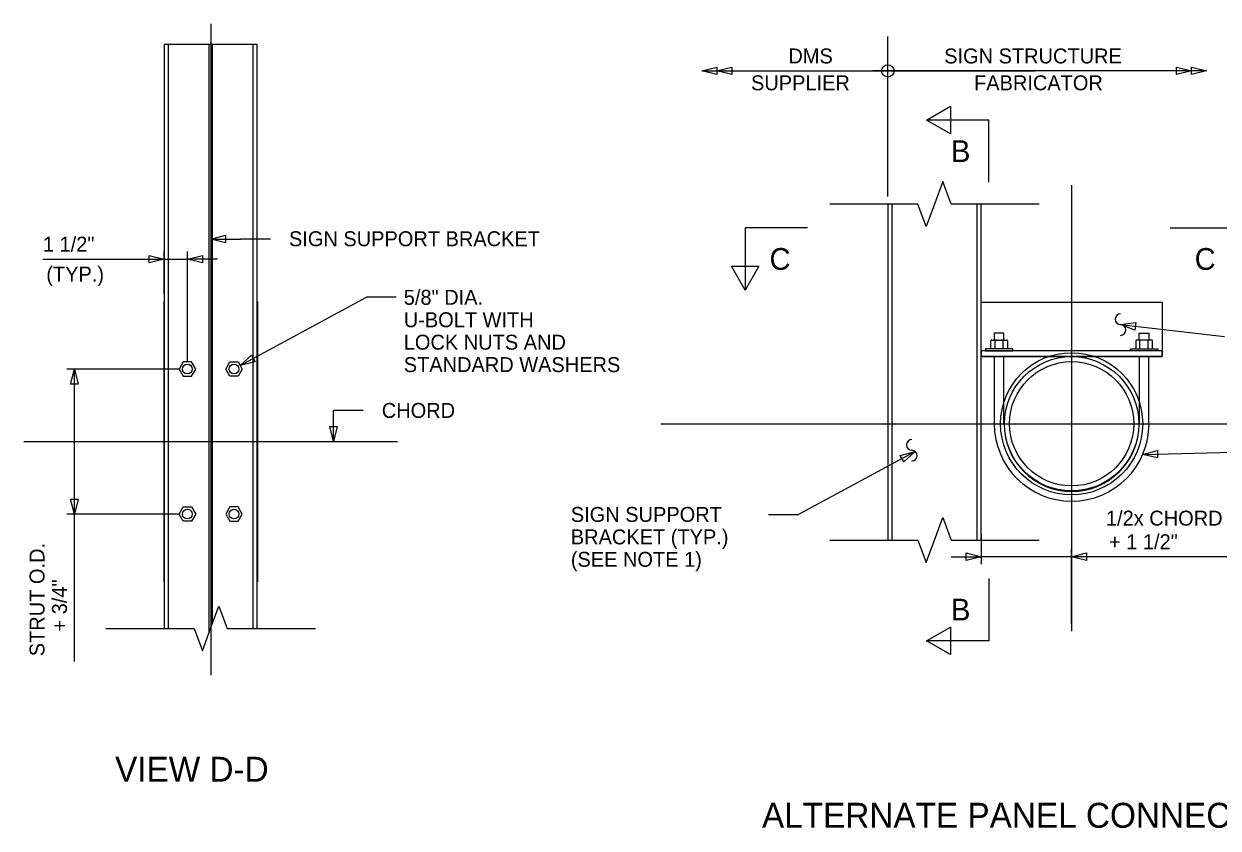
# Model space of a CAD drawing. Extents: x 3831399 to 3833095, y 499014 to 500202.
# Drawn here: x 3832557.6 to 3832797.3, y 499205.3 to 499366.6 of the extents above; entities that cross this region are included whole.
import ezdxf

# ---------------------------------------------------------------- set-up
doc = ezdxf.new("R2010")
doc.units = 0
for name, color, linetype in [('CNTR', 7, 'Continuous'), ('Default', 7, 'Continuous'), ('DIM TXT', 7, 'Continuous'), ('sign', 7, 'Continuous'), ('structure', 7, 'Continuous')]:
    doc.layers.add(name, color=color, linetype=linetype)

msp = doc.modelspace()

# ---------------------------------------------------------------- linework, layer by layer
at = {"layer": 'CNTR'}
for p, q in [((3832595.05, 499366.63), (3832595.05, 499235.97)), ((3832767.85, 499334.27), (3832767.85, 499244.83)), ((3832685.4, 499286.41), (3832811.96, 499286.41)), ((3832557.55, 499282.84), (3832632.55, 499282.84))]:
    msp.add_line(p, q, dxfattribs=at)
at = {"layer": 'Default'}
for p, q in [((3832738.75, 499347.35), (3832743.51, 499350.1)), ((3832743.51, 499350.1), (3832743.51, 499344.6)), ((3832743.51, 499344.6), (3832738.75, 499347.35)), ((3832702.32, 499313.23), (3832699.57, 499318)), ((3832699.57, 499318), (3832705.07, 499318)), ((3832705.07, 499318), (3832702.32, 499313.23)), ((3832738.75, 499242.89), (3832743.51, 499245.64)), ((3832743.51, 499245.64), (3832743.51, 499240.14)), ((3832743.51, 499240.14), (3832738.75, 499242.89))]:
    msp.add_line(p, q, dxfattribs=at)
at = {"layer": 'DIM TXT'}
for p, q in [((3832730.97, 499331.98), (3832730.97, 499364.12)), ((3832693.62, 499357.2), (3832757.55, 499357.2)), ((3832696.62, 499357.2), (3832760.55, 499357.2)), ((3832791.9, 499357.2), (3832727.97, 499357.2)), ((3832794.9, 499357.2), (3832730.97, 499357.2)), ((3832751.25, 499347.35), (3832738.75, 499347.35)), ((3832751.25, 499334.85), (3832751.25, 499347.35)), ((3832741.99, 499334.99), (3832740.32, 499330.48)), ((3832743.66, 499330.48), (3832741.99, 499334.99)), ((3832736.99, 499330.48), (3832719.31, 499330.48)), ((3832738.66, 499325.97), (3832736.99, 499330.48)), ((3832740.32, 499330.48), (3832738.66, 499325.97)), ((3832761.34, 499330.48), (3832743.66, 499330.48)), ((3832714.82, 499325.73), (3832702.32, 499325.73)), ((3832702.32, 499325.73), (3832702.32, 499313.23)), ((3832787.65, 499325.73), (3832800.15, 499325.73)), ((3832595.05, 499323.47), (3832601.05, 499323.47)), ((3832607.05, 499323.47), (3832601.05, 499323.47)), ((3832561.37, 499319.44), (3832585.69, 499319.44)), ((3832585.69, 499312.47), (3832585.69, 499320.94)), ((3832585.69, 499319.44), (3832590.38, 499319.44)), ((3832590.38, 499298.89), (3832590.38, 499320.94)), ((3832596.38, 499319.44), (3832590.38, 499319.44)), ((3832600.99, 499298.08), (3832626.3, 499311.78)), ((3832632.3, 499311.78), (3832626.3, 499311.78)), ((3832777.66, 499306.31), (3832798.52, 499303.9)), ((3832588.88, 499297.39), (3832566.19, 499297.39)), ((3832566.94, 499294.39), (3832567.69, 499297.39)), ((3832567.69, 499268.29), (3832567.69, 499297.39)), ((3832567.69, 499297.39), (3832568.44, 499294.39)), ((3832568.44, 499294.39), (3832566.94, 499294.39)), ((3832619.68, 499282.84), (3832619.68, 499289.09)), ((3832625.68, 499289.09), (3832619.68, 499289.09)), ((3832736.46, 499280.84), (3832713, 499268.22)), ((3832782.09, 499280.23), (3832800.26, 499280.75)), ((3832567.69, 499268.29), (3832566.94, 499271.29)), ((3832566.94, 499271.29), (3832568.44, 499271.29)), ((3832568.44, 499271.29), (3832567.69, 499268.29)), ((3832588.88, 499268.29), (3832566.19, 499268.29)), ((3832567.69, 499238.7), (3832567.69, 499268.29)), ((3832707, 499268.22), (3832713, 499268.22)), ((3832740.32, 499263.08), (3832741.99, 499267.59)), ((3832741.99, 499267.59), (3832743.66, 499263.08)), ((3832749.68, 499264.24), (3832749.68, 499258.25)), ((3832719.31, 499263.08), (3832736.99, 499263.08)), ((3832736.99, 499263.08), (3832738.66, 499258.57)), ((3832738.66, 499258.57), (3832740.32, 499263.08)), ((3832743.66, 499263.08), (3832761.34, 499263.08)), ((3832743.68, 499259.75), (3832749.68, 499259.75)), ((3832767.85, 499259.75), (3832749.68, 499259.75)), ((3832767.85, 499246.33), (3832767.85, 499261.25)), ((3832814.96, 499259.75), (3832767.85, 499259.75)), ((3832751.25, 499255.39), (3832751.25, 499242.89)), ((3832595.04, 499245.34), (3832596.71, 499249.85)), ((3832596.71, 499249.85), (3832598.37, 499245.34)), ((3832574.03, 499245.34), (3832591.71, 499245.34)), ((3832591.71, 499245.34), (3832593.37, 499240.83)), ((3832593.37, 499240.83), (3832595.04, 499245.34)), ((3832598.37, 499245.34), (3832616.06, 499245.34)), ((3832751.25, 499242.89), (3832738.75, 499242.89))]:
    msp.add_line(p, q, dxfattribs=at)
for points in [[(3832696.62, 499356.45), (3832693.62, 499357.2), (3832696.62, 499357.95)], [(3832699.62, 499356.45), (3832696.62, 499357.2), (3832699.62, 499357.95)], [(3832788.9, 499357.95), (3832791.9, 499357.2), (3832788.9, 499356.45)], [(3832791.9, 499357.95), (3832794.9, 499357.2), (3832791.9, 499356.45)], [(3832598.05, 499322.72), (3832595.05, 499323.47), (3832598.05, 499324.22)], [(3832582.69, 499320.19), (3832585.69, 499319.44), (3832582.69, 499318.69)], [(3832593.38, 499318.69), (3832590.38, 499319.44), (3832593.38, 499320.19)], [(3832780.56, 499305.22), (3832777.66, 499306.31), (3832780.73, 499306.71)], [(3832603.98, 499298.85), (3832600.99, 499298.08), (3832603.27, 499300.17)], [(3832620.43, 499285.84), (3832619.68, 499282.84), (3832618.93, 499285.84)], [(3832733.46, 499280.08), (3832736.46, 499280.84), (3832734.17, 499278.75)], [(3832785.11, 499279.57), (3832782.09, 499280.23), (3832785.07, 499281.07)], [(3832746.68, 499260.5), (3832749.68, 499259.75), (3832746.68, 499259)], [(3832770.85, 499259), (3832767.85, 499259.75), (3832770.85, 499260.5)]]:
    msp.add_lwpolyline(points, close=True, dxfattribs=at)
msp.add_circle((3832730.97, 499357.2), 1.25, dxfattribs=at)
for centre, start, end in [((3832777.66, 499307.38), 90, 270), ((3832777.66, 499305.23), 270, 90), ((3832735.78, 499282.17), 90, 270), ((3832735.78, 499280.02), 270, 90)]:
    msp.add_arc(centre, 1.08, start, end, dxfattribs=at)
at = {"layer": 'sign'}
for p, q in [((3832751.64, 499301.45), (3832751.64, 499303.02)), ((3832751.82, 499303.21), (3832754.77, 499303.21)), ((3832754.27, 499304.56), (3832752.32, 499304.56)), ((3832752.32, 499304.56), (3832752.32, 499303.21)), ((3832752.47, 499301.45), (3832752.47, 499303.02)), ((3832754.13, 499301.45), (3832754.13, 499303.02)), ((3832754.27, 499303.21), (3832754.27, 499304.56)), ((3832754.96, 499303.02), (3832754.96, 499301.45)), ((3832780.74, 499303.02), (3832780.74, 499301.45)), ((3832783.87, 499303.21), (3832780.92, 499303.21)), ((3832781.42, 499303.21), (3832781.42, 499304.56)), ((3832781.42, 499304.56), (3832783.37, 499304.56)), ((3832781.57, 499301.45), (3832781.57, 499303.02)), ((3832783.23, 499301.45), (3832783.23, 499303.02)), ((3832783.37, 499304.56), (3832783.37, 499303.21)), ((3832784.06, 499301.45), (3832784.06, 499303.02)), ((3832756.03, 499301.45), (3832750.56, 499301.45)), ((3832750.56, 499301.45), (3832750.56, 499301.06)), ((3832750.56, 499301.06), (3832756.03, 499301.06)), ((3832754.96, 499301.45), (3832751.64, 499301.45)), ((3832752.32, 499299.89), (3832752.32, 499286.41)), ((3832754.27, 499299.89), (3832752.32, 499299.89)), ((3832754.27, 499286.41), (3832754.27, 499299.89)), ((3832756.03, 499301.06), (3832756.03, 499301.45)), ((3832779.66, 499301.06), (3832779.66, 499301.45)), ((3832779.66, 499301.45), (3832785.13, 499301.45)), ((3832785.13, 499301.06), (3832779.66, 499301.06)), ((3832780.74, 499301.45), (3832784.06, 499301.45)), ((3832783.37, 499299.89), (3832781.42, 499299.89)), ((3832781.42, 499299.89), (3832781.42, 499286.41)), ((3832783.37, 499286.41), (3832783.37, 499299.89)), ((3832785.13, 499301.45), (3832785.13, 499301.06)), ((3832589.55, 499298.83), (3832588.72, 499297.39)), ((3832591.21, 499298.83), (3832589.55, 499298.83)), ((3832592.04, 499297.39), (3832591.21, 499298.83)), ((3832598.06, 499297.39), (3832598.89, 499298.83)), ((3832598.89, 499298.83), (3832600.55, 499298.83)), ((3832600.55, 499298.83), (3832601.38, 499297.39)), ((3832588.72, 499297.39), (3832589.55, 499295.96)), ((3832589.55, 499295.96), (3832591.21, 499295.96)), ((3832591.21, 499295.96), (3832592.04, 499297.39)), ((3832598.89, 499295.96), (3832598.06, 499297.39)), ((3832600.55, 499295.96), (3832598.89, 499295.96)), ((3832601.38, 499297.39), (3832600.55, 499295.96)), ((3832588.72, 499268.29), (3832589.55, 499269.73)), ((3832589.55, 499269.73), (3832591.21, 499269.73)), ((3832591.21, 499269.73), (3832592.04, 499268.29)), ((3832598.89, 499269.73), (3832598.06, 499268.29)), ((3832600.55, 499269.73), (3832598.89, 499269.73)), ((3832601.38, 499268.29), (3832600.55, 499269.73)), ((3832589.55, 499266.86), (3832588.72, 499268.29)), ((3832591.21, 499266.86), (3832589.55, 499266.86)), ((3832592.04, 499268.29), (3832591.21, 499266.86)), ((3832598.06, 499268.29), (3832598.89, 499266.86)), ((3832598.89, 499266.86), (3832600.55, 499266.86)), ((3832600.55, 499266.86), (3832601.38, 499268.29))]:
    msp.add_line(p, q, dxfattribs=at)
for centre in [(3832590.38, 499297.39), (3832599.72, 499297.39), (3832590.38, 499268.29), (3832599.72, 499268.29)]:
    msp.add_circle(centre, 0.977, dxfattribs=at)
for centre, radius, start, end in [((3832751.82, 499303.02), 0.187, 90, 180), ((3832752.28, 499303.02), 0.187, 0, 90), ((3832754.31, 499303.02), 0.187, 90, 180), ((3832754.77, 499303.02), 0.187, 0, 90), ((3832780.92, 499303.02), 0.187, 90, 180), ((3832781.38, 499303.02), 0.187, 0, 90), ((3832783.41, 499303.02), 0.187, 90, 180), ((3832783.87, 499303.02), 0.187, 0, 90), ((3832767.85, 499286.41), 15.53, 180, 0), ((3832767.85, 499286.41), 13.57, 180, 0)]:
    msp.add_arc(centre, radius, start, end, dxfattribs=at)
for centre, major_axis, start_param, end_param in [((3832752.98, 499303.02), (-0.518, 0), 4.712389, 6.283185), ((3832753.61, 499303.02), (0.518, 0), 0, 1.570796), ((3832782.08, 499303.02), (-0.518, 0), 4.712389, 6.283185), ((3832782.71, 499303.02), (0.518, 0), 0, 1.570796)]:
    msp.add_ellipse(centre, major_axis=major_axis, ratio=0.362172, start_param=start_param, end_param=end_param, dxfattribs=at)
at = {"layer": 'structure'}
for p, q in [((3832604.4, 499362.53), (3832585.68, 499362.53)), ((3832585.68, 499362.53), (3832585.68, 499245.34)), ((3832603.59, 499362.53), (3832586.49, 499362.53)), ((3832586.49, 499362.53), (3832586.49, 499245.34)), ((3832594.69, 499362.53), (3832594.69, 499244.4)), ((3832595.41, 499246.34), (3832595.41, 499362.53)), ((3832603.59, 499245.34), (3832603.59, 499362.53)), ((3832604.4, 499245.34), (3832604.4, 499362.53)), ((3832730.97, 499330.48), (3832730.97, 499263.08)), ((3832731.78, 499330.48), (3832731.78, 499263.08)), ((3832748.87, 499263.08), (3832748.87, 499330.48)), ((3832749.68, 499263.08), (3832749.68, 499330.48)), ((3832585.69, 499296.32), (3832585.69, 499310.97)), ((3832604.41, 499310.97), (3832604.41, 499254.72)), ((3832749.68, 499310.82), (3832786.01, 499310.82)), ((3832749.68, 499299.89), (3832749.68, 499310.82)), ((3832786.01, 499310.82), (3832786.01, 499299.89)), ((3832786.01, 499301.06), (3832749.68, 499301.06)), ((3832749.68, 499301.06), (3832749.68, 499299.89)), ((3832786.01, 499299.89), (3832749.68, 499299.89)), ((3832749.68, 499299.89), (3832786.01, 499299.89)), ((3832786.01, 499299.89), (3832786.01, 499301.06)), ((3832585.69, 499254.72), (3832585.69, 499296.32))]:
    msp.add_line(p, q, dxfattribs=at)
for radius in [14.26, 13.48, 12.47]:
    msp.add_circle((3832767.85, 499286.41), radius, dxfattribs=at)

# ---------------------------------------------------------------- texts
at = {"layer": 'Default'}
for s, height, p in [('VIEW D-D', 5, (3832575.86, 499214.61)), ('ALTERNATE PANEL CONNECTION DETAIL', 4.9999, (3832705.7, 499205.37))]:
    msp.add_text(s, height=height, dxfattribs=at).set_placement(p)
at = {"layer": 'DIM TXT'}
for s, height, p in [('DMS', 3, (3832711, 499358.7)), ('SIGN STRUCTURE', 2.9999, (3832742.27, 499358.7)), ('SUPPLIER', 3, (3832703.49, 499353.31)), ('FABRICATOR', 3, (3832748.26, 499353.31)), ('B', 4.37, (3832743.64, 499338.92)), ('1 1/2"', 3, (3832561.37, 499320.94)), ('  SIGN SUPPORT BRACKET', 2.9999, (3832608.53, 499322.03)), ('C', 4.37, (3832707.21, 499317.29)), ('C', 4.37, (3832792.54, 499317.29)), ('(TYP.)', 3, (3832562.05, 499314.94)), ('5/8" DIA.', 3, (3832633.8, 499310.28)), ('U-BOLT WITH ', 2.9999, (3832633.8, 499305.78)), ('LOCK NUTS AND', 2.9999, (3832633.8, 499301.28)), ('STANDARD WASHERS', 2.9999, (3832633.8, 499296.78)), ('  CHORD', 3, (3832627.16, 499287.59)), ('SIGN SUPPORT', 2.9999, (3832667.33, 499266.72)), ('1/2x CHORD O.D.', 2.9999, (3832774.74, 499265.98)), ('BRACKET (TYP.)', 2.9999, (3832667.33, 499262.22)), ('+ 1 1/2"', 3, (3832775.35, 499261.25)), ('(SEE NOTE 1)', 2.9999, (3832667.33, 499257.72)), ('B', 4.37, (3832743.64, 499246.95))]:
    msp.add_text(s, height=height, dxfattribs=at).set_placement(p)
for s, p in [('STRUT O.D.', (3832561.69, 499239.77)), ('+ 3/4"', (3832566.19, 499244.73))]:
    msp.add_text(s, height=3, rotation=90, dxfattribs=at).set_placement(p)

doc.saveas('drawing.dxf')
